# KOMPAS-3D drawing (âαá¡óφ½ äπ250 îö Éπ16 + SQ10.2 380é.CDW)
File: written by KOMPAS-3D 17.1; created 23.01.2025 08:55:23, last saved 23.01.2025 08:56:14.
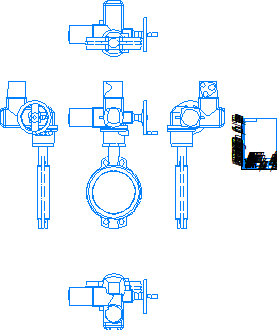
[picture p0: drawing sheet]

Sheet 1: A4, portrait

Title block, sheet 1: material: Сталь 20  ГОСТ 1050-88; mass: 98,86; sheets: 1; sheet format: A4

Views: Вид 1, Спереди, Проекционный вид 2, Проекционный вид 3, Проекционный вид 4, Проекционный вид 5
Referenced files in C:\Клочков АВ\1 Модели разные\Гранвэл\С ПРИВОДАМИ\: Гранвэл Ду250 МФ Ру16 + SQ10.2 380В.m3d
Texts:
  Andrey
  АДЛ
Dimensions and other numbers on the sheet: 1:1; 1; 98,86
